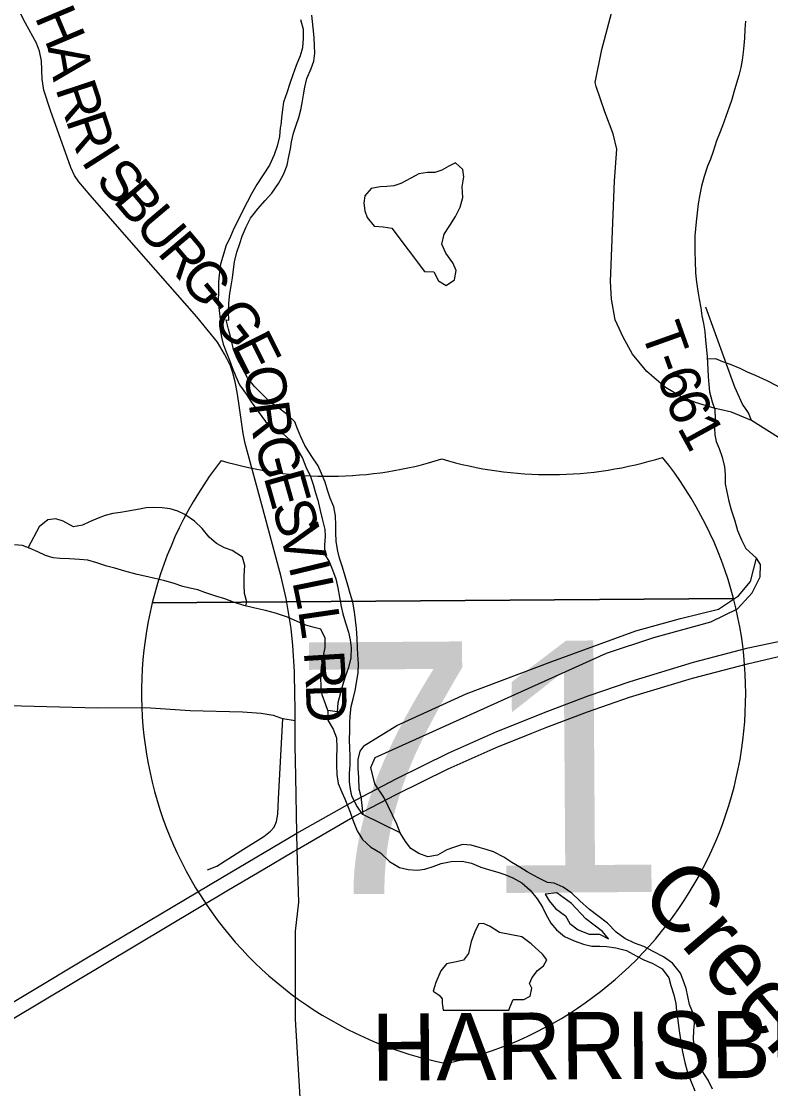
# Model space of a CAD drawing. Extents: x 114604 to 551442, y 316898 to 567001.
# Drawn here: x 156074 to 161654, y 333446 to 341392 of the extents above; entities that cross this region are included whole.
import ezdxf

# ---------------------------------------------------------------- set-up
doc = ezdxf.new("R2010")
doc.units = 0
for name, color, linetype in [('DV_X_County_Line', 7, 'Continuous'), ('GE_P_Alignment', 7, 'Continuous'), ('GE_P_Alignment_1000_Cardinal_Points', 7, 'Continuous'), ('GE_P_Alignment_500_Bearings', 7, 'Continuous'), ('GE_P_Alignment_500_Stations', 7, 'Continuous'), ('MT_X_Edge_Line', 7, 'Continuous'), ('PM_P_Cells', 7, 'Continuous'), ('PM_P_CL_Double_Solid', 7, 'Continuous'), ('PM_P_Crosswalk', 7, 'Continuous'), ('PM_X_Stop_Line', 7, 'Continuous'), ('RD_P_GR_Rt', 7, 'Continuous'), ('SH_Named_Boundary', 7, 'Continuous')]:
    doc.layers.add(name, color=color, linetype=linetype)

msp = doc.modelspace()

# ---------------------------------------------------------------- linework, layer by layer
at = {"layer": 'DV_X_County_Line'}
for points in [[(158027.3, 340252.4), (158053.5, 340320.4), (158065.7, 340386.4), (158079.8, 340442.4), (158086, 340496.4), (158100.1, 340560.5), (158120.3, 340620.5), (158140.5, 340676.5), (158154.6, 340732.5), (158166.7, 340784.5), (158174.9, 340844.5), (158185, 340902.6), (158199.2, 340966.6), (158231.4, 341040.6), (158253.6, 341096.6), (158259.7, 341154.6), (158257.8, 341208.7), (158254, 341272.8), (158248.1, 341342.8), (158238.4, 341437)], [(158152.2, 341407.2), (158172.1, 341333.1), (158171.9, 341267), (158167.7, 341194.9), (158151.6, 341134.9), (158121.4, 341062.9), (158097.2, 340994.9), (158073, 340928.9), (158050.8, 340858.9), (158026.6, 340790.9), (158018.5, 340734.9), (158012.3, 340674.8), (158006.2, 340618.8)], [(158006.2, 340618.8), (158002.1, 340598.8), (157998, 340534.7), (157979.8, 340462.7), (157957.6, 340398.7), (157921.4, 340322.7), (157875.2, 340248.8), (157827, 340178.8), (157788.8, 340108.9), (157756.6, 340044.9), (157718.4, 339974.9), (157694.2, 339923), (157656, 339851), (157631.9, 339791), (157597.7, 339719), (157581.5, 339667), (157557.3, 339585), (157547.1, 339504.9), (157543, 339450.9), (157542.8, 339380.8), (157540.6, 339308.7), (157546.5, 339240.6), (157554.3, 339174.6), (157554.1, 339094.5), (157566, 339040.4), (157577.9, 338988.3), (157603.7, 338920.1), (157623.7, 338870), (157643.5, 338815.9), (157671.4, 338747.8), (157699.3, 338685.6), (157751.1, 338613.4), (157787, 338559.2), (157836.9, 338487), (157892.8, 338412.8), (157956.7, 338360.5), (158024.7, 338320.3), (158076.6, 338274.1), (158128.5, 338207.9), (158168.4, 338139.7), (158192.2, 338075.6), (158228.1, 338003.4), (158248, 337945.3), (158265.8, 337881.1), (158281.7, 337827), (158299.6, 337750.9), (158315.4, 337688.8), (158333.2, 337608.6), (158337.1, 337558.6), (158331, 337492.5), (158334.8, 337420.4), (158366.7, 337370.3), (158390.6, 337310.1), (158416.4, 337242), (158430.3, 337175.9), (158444.1, 337105.8), (158456, 337035.6), (158467.9, 336981.5), (158487.7, 336915.4), (158509.6, 336845.3), (158523.4, 336787.2), (158529.3, 336727.1), (158527.1, 336653), (158510.9, 336582.9), (158486.7, 336512.9), (158466.6, 336446.9), (158450.4, 336392.9), (158432.2, 336318.9), (158426, 336250.8), (158356, 336261), (158357.8, 336188.9), (158395.7, 336122.7), (158421.6, 336058.6), (158423.4, 335982.5), (158421.2, 335912.4), (158421.1, 335854.3), (158424.9, 335786.2), (158434.8, 335718.1), (158460.6, 335654), (158482.5, 335603.8), (158522.3, 335505.6), (158546.2, 335439.5), (158574, 335365.3), (158613.9, 335301.1), (158677.8, 335244.8), (158747.8, 335202.6), (158815.7, 335136.3), (158889.6, 335092.1), (158955.7, 335077.9), (159021.7, 335073.7), (159079.8, 335081.5), (159139.9, 335101.4), (159200, 335123.2), (159276.1, 335137), (159358.2, 335138.8), (159426.2, 335124.6), (159496.2, 335096.4), (159560.2, 335076.2), (159622.2, 335058), (159674.2, 335039.8), (159734.2, 335015.6)], [(157620.4, 339166.4), (157616.5, 339226.4), (157618.7, 339294.5), (157626.8, 339366.6), (157637, 339422.6), (157647.1, 339482.6), (157655.3, 339544.7), (157661.4, 339600.7), (157679.6, 339672.7), (157701.8, 339738.7), (157718, 339792.8), (157748.2, 339862.7), (157780.3, 339926.7), (157836.5, 339996.6), (157890.7, 340058.5), (157940.9, 340112.5), (157989.1, 340184.4), (158027.3, 340252.4)], [(158616.4, 335487.3), (158570.5, 335555.5), (158536.6, 335625.7), (158524.7, 335675.8), (158518.9, 335729.9), (158519, 335792), (158523.2, 335854), (158523.3, 335926.1), (158519.5, 335976.2), (158517.6, 336048.3), (158519.8, 336104.3), (158519.9, 336170.4), (158522.1, 336220.5), (158530.2, 336290.5), (158544.4, 336348.6), (158560.6, 336410.6), (158582.9, 336542.7), (158585.1, 336608.8), (158581.2, 336678.9), (158577.3, 336728.9), (158575.5, 336797), (158569.7, 336871.1), (158556, 336997.3), (158542.1, 337067.4), (158522.3, 337133.6), (158506.4, 337195.7), (158486.6, 337261.8), (158464.7, 337329.9), (158442.8, 337396.1), (158431, 337448.2), (158419.1, 337520.3), (158417.3, 337586.4), (158417.4, 337642.4), (158413.6, 337710.5), (158401.7, 337778.6), (158373.9, 337842.8), (158354, 337902.9), (158336.1, 337961), (158310.2, 338027.2), (158284.3, 338083.3), (158236.5, 338153.5), (158186.6, 338235.7), (158154.8, 338299.9), (158130.9, 338358), (158111, 338410.2), (158053.1, 338466.4), (157981.1, 338520.6), (157921.2, 338560.9), (157859.3, 338623.1), (157811.3, 338673.3), (157759.5, 338739.5), (157717.6, 338811.7), (157681.7, 338881.9), (157653.9, 338950), (157636, 339026.2), (157616.2, 339100.3), (157600.3, 339170.4), (157620.4, 339166.4)], [(158896.3, 335350.4), (158616.4, 335487.3)], [(161221.7, 333443.4), (161189.8, 333509.6), (161144, 333579.8), (161122.1, 333637.9), (161108.2, 333692), (161086.3, 333748.2), (161080.5, 333814.3), (161082.7, 333882.4), (161086.8, 333932.4), (161079, 334000.5), (161049.1, 334072.7), (161025.4, 334192.9), (161001.5, 334255.1), (160981.6, 334307.2), (160923.7, 334381.5), (160855.8, 334427.7), (160779.8, 334468), (160709.9, 334504.2), (160639.9, 334530.5), (160567.9, 334564.7), (160503.9, 334610.9), (160440, 334677.2), (160368.1, 334733.5), (160304.2, 334779.7), (160234.2, 334844), (160174.3, 334902.2), (160108.4, 334946.5), (160042.4, 334976.7), (159992.4, 334980.8), (159922.4, 335017.1), (159840.4, 335059.4), (159786.5, 335095.6), (159726.5, 335129.8), (159666.5, 335170), (159590.6, 335210.3), (159536.6, 335226.4), (159484.6, 335242.6), (159424.5, 335258.8), (159360.5, 335263), (159292.4, 335241.1), (159242.3, 335223.2), (159172.1, 335183.4), (159102, 335171.6), (159034, 335197.8), (158974.1, 335234), (158934.2, 335286.2), (158896.3, 335350.4)], [(159734.2, 335015.6), (159802.2, 334979.4), (159864.1, 334923.1), (159916, 334858.9), (159955.9, 334796.7), (159979.8, 334744.6), (160017.7, 334678.4), (160059.6, 334628.2), (160119.5, 334580), (160191.5, 334545.7), (160259.5, 334521.5), (160323.5, 334507.3), (160381.6, 334507.1), (160433.6, 334505), (160501.6, 334494.8), (160579.7, 334474.5), (160653.6, 334436.3), (160709.6, 334406.1), (160775.6, 334377.9), (160845.6, 334339.6), (160895.4, 334271.4), (160911.3, 334213.3), (160933.2, 334145.1), (160947, 334081), (160952.9, 334024.9), (160962.7, 333956.8), (160970.6, 333894.7), (160978.5, 333844.6), (160988.3, 333778.5), (160998.2, 333720.4), (161014, 333640.2), (161035.8, 333566.1), (161061.7, 333497.9), (161089.6, 333429.7)], [(160447.8, 334561), (160401.8, 334617.2), (160278, 334709.7), (160170.1, 334824.1), (160062.2, 334904.5), (159974.1, 334894.8)], [(159974.1, 334894.8), (160004, 334844.6), (160051.9, 334788.4), (160125.9, 334734.1), (160157.8, 334676), (160219.7, 334627.8), (160301.7, 334597.5), (160379.8, 334595.3), (160447.8, 334561)]]:
    msp.add_lwpolyline(points, dxfattribs=at)
at = {"layer": 'GE_P_Alignment'}
for p, q in [((157049.4, 337064.1), (161377.9, 337095.2)), ((161377.9, 337095.2), (157049.4, 337064.1)), ((161377.9, 337095.2), (157049.4, 337064.1))]:
    msp.add_line(p, q, dxfattribs=at)
for centre, start, end in [((159781.2, 336394), 142.08127, 166.21896), ((158364.8, 340818.4), 253.42141, 287.40326), ((160008.6, 340830.2), 253.42142, 287.40327), ((158656.1, 336385.9), 14.60571, 38.7434), ((158656.1, 336385.9), 281.94931, 14.60571), ((159781.2, 336394), 166.21897, 258.87536)]:
    msp.add_arc(centre, 2812.7, start, end, dxfattribs=at)
at = {"layer": 'GE_P_Alignment_1000_Cardinal_Points'}
for points in [[(161511.5, 338420.7), (161489.1, 338477.8), (161444.6, 338543.4), (161386.5, 338668.5), (161170.3, 339264.3)], [(150130.8, 336580.5), (150855.4, 336511.5), (151644, 336458.5), (151724.1, 336458.4), (152082.3, 336444), (152878.9, 336405), (154033.8, 336361.6), (155232.8, 336340.2), (155883.3, 336301.4), (156641.9, 336280.6), (157000.2, 336284.2), (157332.4, 336261.8), (157720.7, 336251.4), (157860.8, 336241.2), (157948.9, 336227), (158005, 336207), (158021.5, 336201.6), (158113.5, 336187.5)], [(157459.5, 335075.7), (157529.5, 335101.8), (157709.5, 335218.1), (157879.5, 335324.4), (157929.4, 335364.5), (157957.4, 335392.6), (157975.4, 335434.7), (157983.3, 335490.8), (157989.1, 335603), (158021.5, 336201.6)]]:
    msp.add_lwpolyline(points, dxfattribs=at)
at = {"layer": 'GE_P_Alignment_500_Bearings'}
for points in [[(161276.7, 338502), (161241.3, 338510.1), (161093.6, 338555.2), (160981, 338602.8), (160870.6, 338665.8), (160731.1, 338785.8), (160624.5, 338914.9), (160555.4, 339039.8), (160495.1, 339169.2), (160469.8, 339323), (160462.2, 339455), (160491.6, 340205.5), (160507.7, 340439.9), (160481.6, 340554.1), (160419.6, 340718.5), (160355.6, 340906.8), (160347.6, 340936.9), (160397.7, 341183.2), (160541.9, 341726)], [(158112.5, 336292.5), (158111.7, 336371.2), (158107.7, 336553.1), (158096.8, 336746.3), (158084.5, 336871.5), (158046.4, 337095), (158009.5, 337257.5), (157872.7, 337765.7), (157742.1, 338250.5), (157726.8, 338322.6), (157693.8, 338548.7), (157681.1, 338632.1), (157666.6, 338709.5), (157648.7, 338774.7), (157628.2, 338834.6), (157586.8, 338913.5), (157534.8, 339002.8), (157381.1, 339191.4), (156858.9, 339786.5), (156586.8, 340098.8), (156501.7, 340196.5), (156470, 340245), (156442.6, 340303.2), (156291.5, 340729.5), (156242.6, 340879.7), (156229.8, 340962.3), (156224.5, 341098.9), (156210, 341170.2), (156187, 341231), (156104.9, 341379.2), (155969.8, 341648.1)], [(162273.2, 337704.3), (162236, 337834.6), (162206.3, 337908.2), (162182.6, 337945.9), (162156.2, 337984.2), (162102.3, 338031.7), (162032.2, 338082.3), (161938.4, 338146.5), (161712.7, 338294.6), (161511.5, 338420.7), (161362.6, 338482.3), (161276.7, 338502)], [(158116.6, 334052), (158116.7, 334619.8), (158139.9, 334834.2), (158128.7, 335227.4), (158126.3, 335348.7), (158117.9, 335770.7), (158113.4, 336000.4), (158113.5, 336187.5), (158112.5, 336292.5)], [(158137.4, 332695.5), (158148.4, 332889.6), (158159.4, 333213.9), (158116.6, 333962.5), (158116.6, 333999.9), (158116.6, 334052)]]:
    msp.add_lwpolyline(points, dxfattribs=at)
at = {"layer": 'GE_P_Alignment_500_Stations'}
msp.add_line((157875.7, 335078.2), (158101.6, 335211.4), dxfattribs=at)
for points in [[(159877, 336094), (159988.7, 336138.6), (160290.2, 336252.7), (160602.8, 336359.8), (161072.9, 336502.2), (161480.7, 336609.4), (161923.3, 336714), (162445.2, 336806.7), (162761.8, 336854.8), (162787.7, 336857.9)], [(155700.3, 333905.3), (156550, 334411.8), (157571.3, 335020.9), (158126.3, 335348.7), (158562.2, 335593.5), (158871, 335755.5), (159257.8, 335945.7), (159615.7, 336105.8), (159994.5, 336257), (160296, 336371.1), (160608.6, 336478.2), (161078.7, 336620.6), (161486.6, 336727.8), (161934.8, 336822.9)], [(158101.6, 335211.4), (158128.7, 335227.4), (158556.4, 335475.1), (158865.2, 335637.1), (159252, 335827.3), (159609.8, 335987.4), (159877, 336094)], [(151590.4, 331333.2), (153437.6, 332434.6), (154204, 332893.5), (154889.1, 333295.6), (155774.7, 333827.6), (157618.1, 334926.3), (157875.7, 335078.2)]]:
    msp.add_lwpolyline(points, dxfattribs=at)
at = {"layer": 'MT_X_Edge_Line'}
for points in [[(159076.3, 339529.2), (159146.4, 339526.6), (159181.9, 339460.2), (159237.7, 339425.6), (159300.2, 339467.2), (159312.8, 339537.2), (159287.2, 339595.6), (159235.7, 339666.1), (159206.2, 339734.5), (159222.9, 339808.6), (159265.5, 339872.3), (159308.1, 339940.1), (159342.7, 340009.9), (159361.4, 340081.9), (159358, 340160.1), (159370.6, 340234.1), (159361.1, 340288.3), (159307.4, 340338.9), (159257.1, 340313.3), (159204.8, 340283.7), (159154.6, 340268.1), (159098.5, 340266.6), (159034.3, 340257.1), (158974, 340225.6), (158901.5, 340184.1), (158849.3, 340166.5), (158797.2, 340163), (158747.1, 340159.4), (158678.9, 340148), (158632.3, 340092.3), (158623.9, 340038.2), (158631.4, 339982), (158649, 339931.8), (158702.6, 339867.2), (158768.6, 339862.6), (158832.6, 339852)], [(158832.6, 339852), (159076.3, 339529.2)], [(159705.4, 334029.7), (159715.7, 334063.7), (159736.1, 334109.6), (159764.1, 334109.4), (159816.2, 334110.9), (159862.5, 334134.6), (159875, 334194.6), (159859.3, 334228.8), (159877.7, 334272.8), (159918.2, 334326.6), (159962.5, 334360.3), (159986.9, 334406.2), (159955.2, 334446.5), (159871.8, 334525.4), (159802.1, 334576.2), (159636.1, 334607.7), (159566.3, 334652.4), (159516.5, 334676.8), (159480.4, 334673.2), (159456, 334627.3), (159425.2, 334541.3), (159404.4, 334453.3), (159368, 334403.5), (159315.8, 334389.9), (159241.5, 334376.5), (159199, 334322.8), (159160.3, 334236.9), (159141.7, 334172.9), (159185.5, 334142.5), (159209.3, 334114.2), (159209, 334082.1), (159216.6, 334030)], [(159216.6, 334030), (159705.4, 334029.7)]]:
    msp.add_lwpolyline(points, dxfattribs=at)
at = {"layer": 'PM_P_Cells'}
for points in [[(161467.5, 341392.4), (161463, 341334.3), (161458.4, 341268.2), (161454, 341212.1), (161449.5, 341162.1), (161443, 341104), (161432.6, 341048), (161418.1, 340990), (161399.5, 340932), (161381, 340866), (161364.5, 340810.1), (161346, 340754.1), (161321.4, 340684.2), (161294.7, 340614.3), (161274.2, 340558.4), (161251.7, 340502.4), (161225.1, 340424.5), (161206.6, 340366.5), (161184.1, 340314.6), (161159.4, 340236.7), (161138.8, 340164.7), (161126.2, 340102.7), (161113.6, 340032.7), (161107.1, 339966.6), (161098.5, 339898.5), (161094.1, 339848.5), (161089.6, 339796.4), (161088.6, 339678.2), (161092, 339604), (161095.4, 339521.8), (161098.9, 339469.6), (161112.2, 339383.3), (161121.7, 339325.1), (161133.2, 339258.9), (161142.7, 339200.7)], [(161142.7, 339200.7), (161154.3, 339142.5), (161163.8, 339084.3), (161169.3, 339018.1), (161176.7, 338945.9), (161182.2, 338893.7), (161187.5, 338801.5), (161189.1, 338749.4), (161192.6, 338689.2), (161198.1, 338633), (161217.5, 338560.7), (161239.1, 338502.4), (161240.5, 338430.2), (161235.9, 338364.2), (161237.5, 338314), (161249.1, 338263.8), (161270.7, 338211.5), (161292.2, 338147.2), (161309.6, 338074.9), (161315.2, 338018.7), (161316.6, 337948.6), (161328.1, 337890.3), (161341.6, 337820.1), (161361, 337755.8), (161386.4, 337673.4), (161407.8, 337601), (161437.3, 337532.6), (161468.8, 337468.2), (161548.3, 337395.4)], [(161183.1, 338879.7), (161244.3, 338883.2), (161296.1, 338858.7), (161352.1, 338840.1), (161423.9, 338809.5), (161479.8, 338782.9), (161539.7, 338758.4), (161625.5, 338719.5), (161697.3, 338680.8), (161772, 338643.3)], [(157746.5, 337040.2), (157753.8, 337071.5), (157736.3, 337131.8), (157732.8, 337193.9), (157733.4, 337264.1), (157738, 337340.2), (157720.5, 337402.5), (157644.8, 337453.3), (157586.9, 337473.8), (157527.1, 337504.4), (157473.4, 337553), (157421.8, 337617.6), (157364.2, 337672.2), (157292.5, 337720.9), (157240.6, 337745.4), (157182.7, 337761.9), (157122.7, 337770.5), (157058.6, 337773), (157004.5, 337769.5), (156954.3, 337759.9), (156870.1, 337744.6), (156811.9, 337735.1), (156755.7, 337727.6), (156699.5, 337714), (156645.3, 337694.5), (156583, 337667), (156530.7, 337641.3), (156462.5, 337629.9), (156386.7, 337670.7), (156330.8, 337689.2), (156272.6, 337681.7), (156208.1, 337630.1), (156124.5, 337474.1)], [(158356, 336261), (158342.3, 336304.7), (158314.9, 336379.1), (158307.3, 336433.3), (158304, 336513.5), (158310.6, 336587.6), (158321.2, 336655.7), (158335.8, 336731.7), (158336.4, 336799.8), (158304.9, 336866.3), (158245, 336882.8), (158193, 336897.3), (158129.1, 336923.9), (158055.3, 336956.6), (157967.4, 336985.4), (157891.5, 337006.2), (157803.5, 337027), (157731.5, 337043.6), (157653.6, 337068.4), (157589.7, 337093), (157523.8, 337111.6), (157441.9, 337140.3), (157388, 337158.9), (157330, 337173.4), (157276, 337185.9), (157204.1, 337208.6), (157142.2, 337227.1), (157016.2, 337256.3), (156936.2, 337273), (156846.3, 337299.9), (156770.4, 337320.6), (156710.4, 337337.1), (156636.5, 337361.8), (156568.6, 337380.4), (156508.5, 337387), (156432.4, 337391.7), (156362.4, 337394.3), (156310.3, 337398.7), (156254.4, 337415.3), (156196.5, 337443.8), (156140.6, 337468.4), (156082.7, 337488.9), (156024.7, 337495.4)], [(158624.2, 335999.6), (158869.8, 336149.8), (159386.6, 336385.8), (160023.6, 336626.9), (160650.4, 336853.9), (160983.7, 336947.3), (161264.7, 337017), (161415.8, 337115.9), (161504.8, 337221.4), (161548.3, 337395.4)], [(158676.9, 335836.8), (158709.6, 335910.6), (160432.7, 336689.5), (160784.2, 336804.7), (161209.8, 336921.3), (161406.9, 337017.8), (161516.1, 337137.1), (161577.2, 337256.8), (161578, 337349), (161548.3, 337395.4)], [(158624.2, 335999.6), (158595.8, 335959.7), (158581.3, 335897.7), (158580.7, 335831.6), (158584.1, 335761.4), (158587.4, 335679.2), (158603, 335620.9), (158616.4, 335487.3)], [(158896.3, 335350.4), (158871.4, 335414.5), (158773.2, 335615.4), (158707.9, 335716.2), (158676.9, 335836.8)], [(158896.3, 335350.4), (158616.4, 335487.3)]]:
    msp.add_lwpolyline(points, dxfattribs=at)

# ---------------------------------------------------------------- texts
at = {"layer": 'GE_P_Alignment'}
msp.add_text('71', height=1875.14, rotation=0.41234, dxfattribs=at).set_placement((158101, 334891.8))
at = {"layer": 'PM_P_CL_Double_Solid'}
for s, rotation, p in [('H', 292.91179, (156171, 341426)), ('A', 279.81651, (156268.7, 341200.1)), ('R', 288.30455, (156325.5, 340893)), ('R', 288.41582, (156403.1, 340658.4)), ('I', 302.46949, (156515.4, 340352.2)), ('S', 312.40692, (156616, 340203.2)), ('B', 310.2361, (156750.6, 340056)), ('U', 310.19291, (156909.7, 339867.9)), ('R', 310.19188, (157080.1, 339666.2)), ('G', 309.92379, (157238.9, 339478.3)), ('-', 308.77953, (157407.3, 339277)), ('G', 307.22683, (157483.2, 339182.7)), ('E', 296.57776, (157635.1, 338985)), ('O', 278.53726, (157728, 338808)), ('R', 277.44172, (157767, 338548.4)), ('G', 284.8797, (157807.1, 338262.3)), ('E', 285.87055, (157876.4, 338001.7)), ('S', 285.86559, (157937.8, 337785.8)), ('V', 285.42047, (157993, 337591.7)), ('I', 283.69597, (158062.6, 337339.5)), ('L', 281.52348, (158091.1, 337222.8)), ('L', 278.34878, (158135.2, 337007.2)), ('R', 273.55189, (158177.8, 336700)), ('D', 271.45239, (158192.9, 336456.9))]:
    msp.add_text(s, height=300, rotation=rotation, dxfattribs=at).set_placement(p)
at = {"layer": 'PM_P_Crosswalk'}
for s, rotation, p in [('T', 289.61373, (160685.6, 339087.7)), ('-', 289.66983, (160761, 338876)), ('6', 289.90382, (160802.9, 338758.7)), ('6', 291.31819, (160868.7, 338577.4)), ('1', 298.73108, (160953.8, 338366.9))]:
    msp.add_text(s, height=300, rotation=rotation, dxfattribs=at).set_placement(p)
at = {"layer": 'PM_X_Stop_Line'}
for s, p in [('-', (159222.1, 335883.8)), ('.', (159222.2, 335883.8)), (',', (159222.1, 335883.8)), ('71', (159019.3, 335675.3))]:
    msp.add_text(s, height=1, rotation=0.41234, dxfattribs=at).set_placement(p)
at = {"layer": 'RD_P_GR_Rt'}
msp.add_text('Creek', height=500.09, rotation=310.40292, dxfattribs=at).set_placement((160664, 334888.4))
at = {"layer": 'SH_Named_Boundary'}
msp.add_text('HARRISBURG', height=500.04, rotation=0.41234, dxfattribs=at).set_placement((158683.2, 333504.8))

doc.saveas('drawing.dxf')
